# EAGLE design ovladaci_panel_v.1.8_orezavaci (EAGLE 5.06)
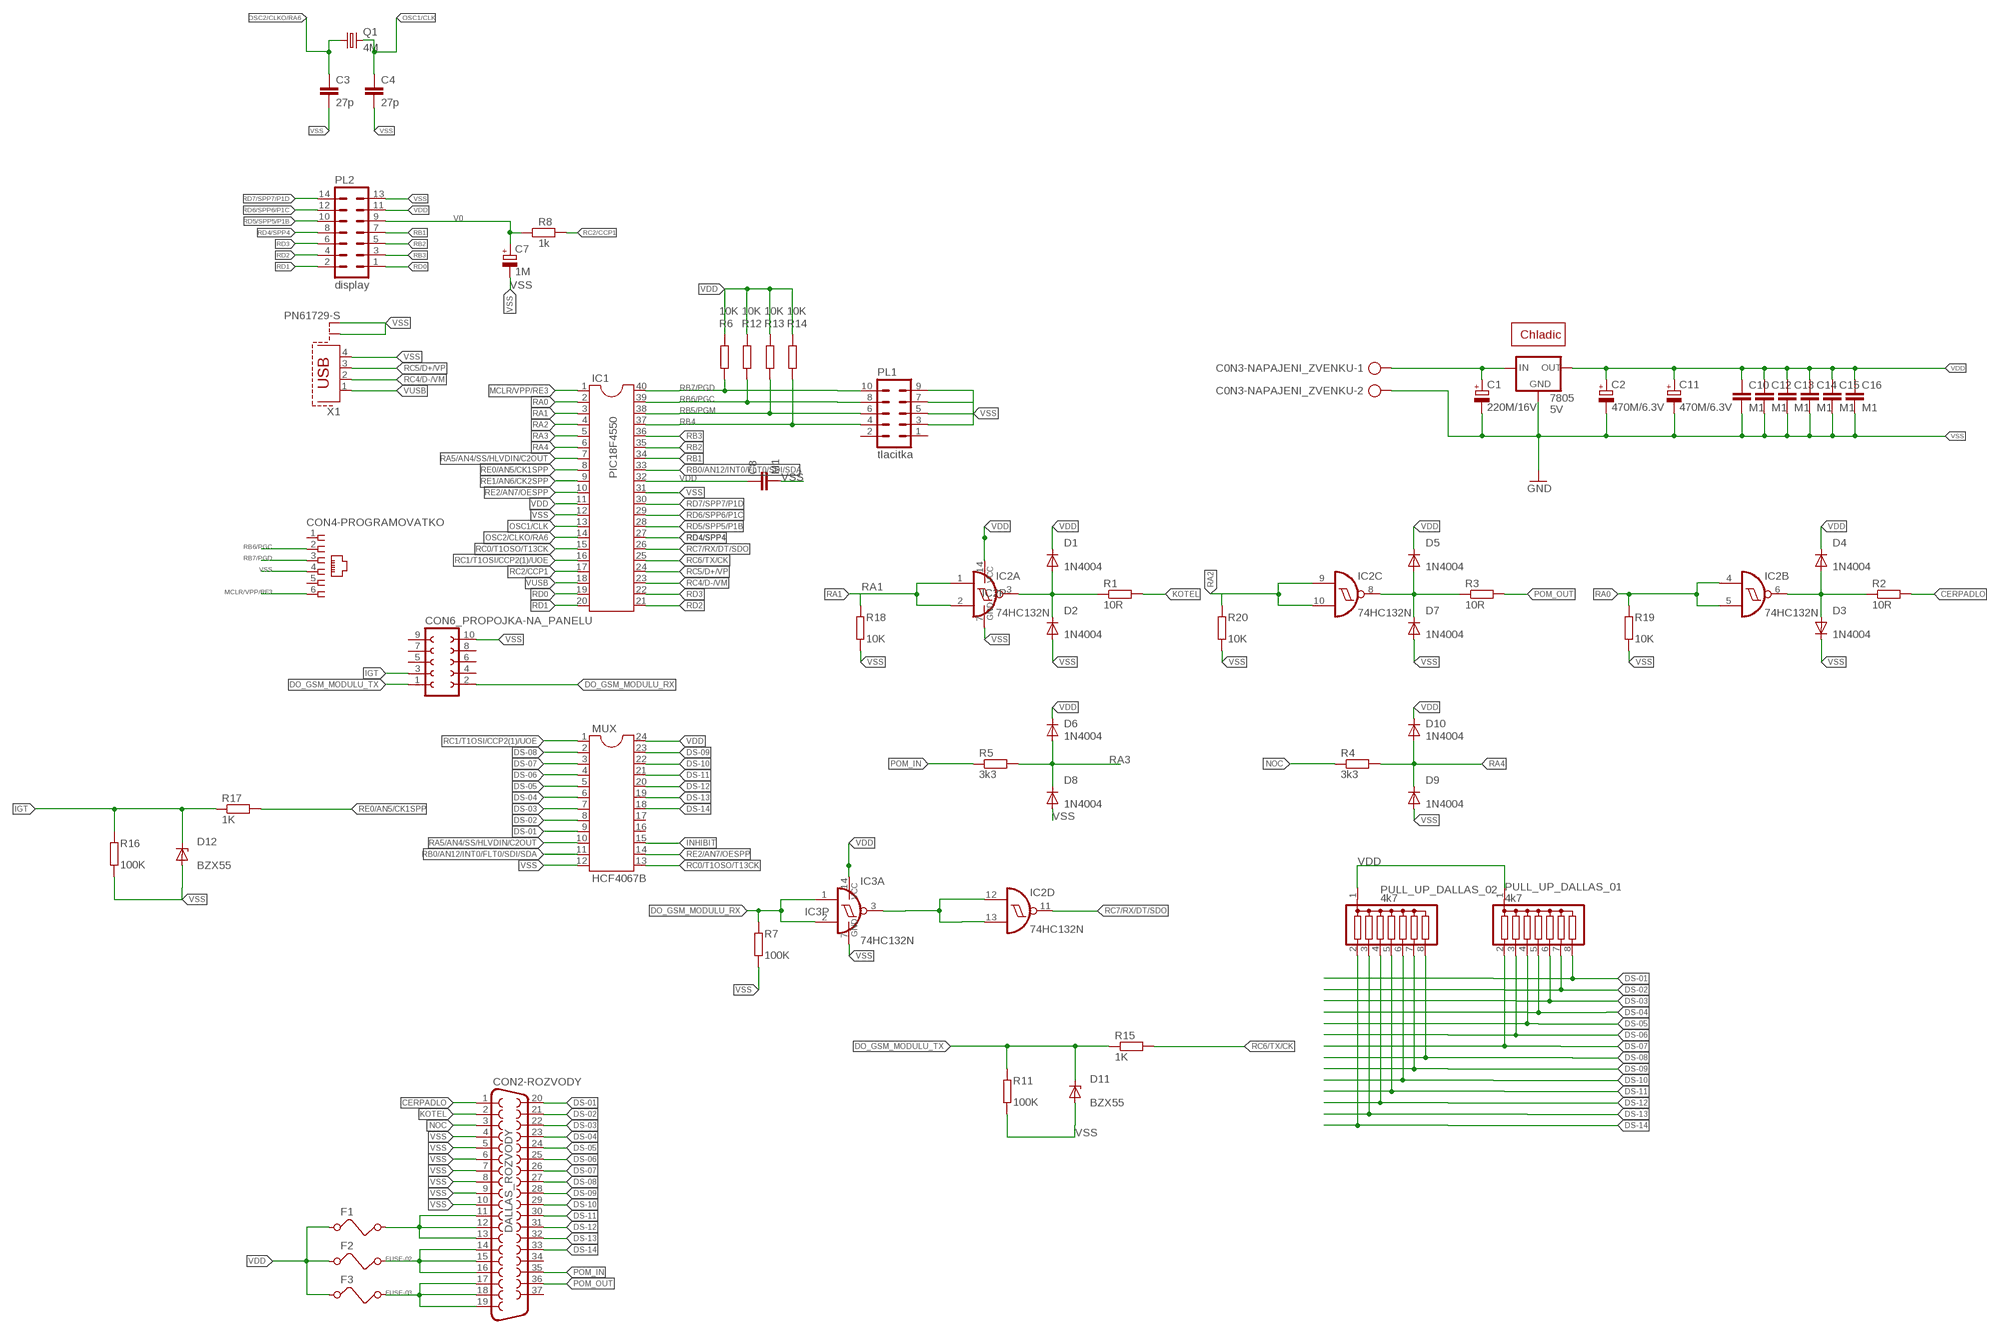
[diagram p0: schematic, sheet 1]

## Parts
7805  5V  78XXL  [78XXL]
C0N3-NAPAJENI_ZVENKU  AK500/2-H  [AK500/2-H]
C1  220M/16V  CPOL-EUE5-13  [E5-13]
C2  470M/6.3V  CPOL-EUE5-13  [E5-13]
C3  27p  C-EU025-025X050  [C025-025X050]
C4  27p  C-EU025-025X050  [C025-025X050]
C7  1M  CPOL-EUE2.5-5  [E2,5-5]
C8  M1  C-EU025-025X050  [C025-025X050]
C10  M1  C-EU025-025X050  [C025-025X050]
C11  470M/6.3V  CPOL-EUE5-13  [E5-13]
C12  M1  C-EU025-025X050  [C025-025X050]
C13  M1  C-EU025-025X050  [C025-025X050]
C14  M1  C-EU025-025X050  [C025-025X050]
C15  M1  C-EU025-025X050  [C025-025X050]
C16  M1  C-EU025-025X050  [C025-025X050]
CON2-ROZVODY  DALLAS_ROZVODY  F37HP  [F37HP]
CON4-PROGRAMOVATKO  520250-3  [520250-3]
CON6_PROPOJKA-NA_PANELU  FE05-2W  [FE05-2W]
D1  1N4004  [DO41-10]
D2  1N4004  [DO41-10]
D3  1N4004  [DO41-10]
D4  1N4004  [DO41-10]
D5  1N4004  [DO41-10]
D6  1N4004  [DO41-10]
D7  1N4004  [DO41-10]
D8  1N4004  [DO41-10]
D9  1N4004  [DO41-10]
D10  1N4004  [DO41-10]
D11  BZX55  [DO35Z10]
D12  BZX55  [DO35Z10]
F1  FUSE  [FUSE]
F2  FUSE  [FUSE]
F3  FUSE  [FUSE]
IC1  PIC18F4550  DIL40  [DIL40]
IC2  74HC132N  [DIL14]
IC3  74HC132N  [DIL14]
MUX  HCF4067B  DIL24-6  [DIL24-6]
PL1  tlacitka  10V  [10V]
PL2  display  14V  [14V]
PULL_UP_DALLAS_01  4k7  G07R  [SIL8]
PULL_UP_DALLAS_02  4k7  G07R  [SIL8]
Q1  4M  CRYSTALHC49S  [HC49/S]
R1  10R  R-EU_0207/10  [0207/10]
R2  10R  R-EU_0207/10  [0207/10]
R3  10R  R-EU_0207/10  [0207/10]
R4  3k3  R-EU_0207/10  [0207/10]
R5  3k3  R-EU_0207/10  [0207/10]
R6  10K  R-EU_0207/10  [0207/10]
R7  100K  R-EU_0207/10  [0207/10]
R8  1k  R-EU_0207/10  [0207/10]
R11  100K  R-EU_0207/10  [0207/10]
R12  10K  R-EU_0207/10  [0207/10]
R13  10K  R-EU_0207/10  [0207/10]
R14  10K  R-EU_0207/10  [0207/10]
R15  1K  R-EU_0207/10  [0207/10]
R16  100K  R-EU_0207/10  [0207/10]
R17  1K  R-EU_0207/10  [0207/10]
R18  10K  R-EU_0207/10  [0207/10]
R19  10K  R-EU_0207/10  [0207/10]
R20  10K  R-EU_0207/10  [0207/10]
U$1  CHLADIC  [CHLADIC]
X1  PN61729-S  [PN61729-S]

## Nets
CERPADLO: CON2-ROZVODY.1 R2.2
CESTA: IC2.12(D:I0) IC2.13(D:I1) IC3.3(A:O)
DO_GSM_MODULU_RX: CON6_PROPOJKA-NA_PANELU.2 IC3.1(A:I0) IC3.2(A:I1) R7.2
DO_GSM_MODULU_TX: CON6_PROPOJKA-NA_PANELU.1 D11.C R11.2 R15.1
DS-01: CON2-ROZVODY.20 MUX.9 PULL_UP_DALLAS_01.8
DS-02: CON2-ROZVODY.21 MUX.8 PULL_UP_DALLAS_01.7
DS-03: CON2-ROZVODY.22 MUX.7 PULL_UP_DALLAS_01.6
DS-04: CON2-ROZVODY.23 MUX.6 PULL_UP_DALLAS_01.5
DS-05: CON2-ROZVODY.24 MUX.5 PULL_UP_DALLAS_01.4
DS-06: CON2-ROZVODY.25 MUX.4 PULL_UP_DALLAS_01.3
DS-07: CON2-ROZVODY.26 MUX.3 PULL_UP_DALLAS_01.2
DS-08: CON2-ROZVODY.27 MUX.2 PULL_UP_DALLAS_02.8
DS-09: CON2-ROZVODY.28 MUX.23 PULL_UP_DALLAS_02.7
DS-10: CON2-ROZVODY.29 MUX.22 PULL_UP_DALLAS_02.6
DS-11: CON2-ROZVODY.30 MUX.21 PULL_UP_DALLAS_02.5
DS-12: CON2-ROZVODY.31 MUX.20 PULL_UP_DALLAS_02.4
DS-13: CON2-ROZVODY.32 MUX.19 PULL_UP_DALLAS_02.3
DS-14: CON2-ROZVODY.33 MUX.18 PULL_UP_DALLAS_02.2
FUSE-02: CON2-ROZVODY.14 CON2-ROZVODY.15 CON2-ROZVODY.16 F2.2
FUSE-03: CON2-ROZVODY.17 CON2-ROZVODY.18 CON2-ROZVODY.19 F3.2
IGT: CON6_PROPOJKA-NA_PANELU.3 D12.C R16.2 R17.1
INHIBIT: MUX.15
KOTEL: CON2-ROZVODY.2 R1.2
MCLR/VPP/RE3: CON4-PROGRAMOVATKO.6 IC1.1
N$1: 7805.IN C0N3-NAPAJENI_ZVENKU.1 C1.+
N$2: D1.A D2.C IC2.3(A:O) R1.1
N$5: D3.A D4.A IC2.6(B:O) R2.1
N$6: D5.A D7.C IC2.8(C:O) R3.1
N$10: CON2-ROZVODY.11 CON2-ROZVODY.12 CON2-ROZVODY.13 F1.2
NOC: CON2-ROZVODY.3 R4.1
OSC1/CLK: C4.1 IC1.13 Q1.2
OSC2/CLKO/RA6: C3.1 IC1.14 Q1.1
POM_IN: CON2-ROZVODY.35 R5.1
POM_OUT: CON2-ROZVODY.36 R3.2
RA0: IC1.2 IC2.4(B:I0) IC2.5(B:I1) R19.2
RA1: IC1.3 IC2.1(A:I0) IC2.2(A:I1) R18.2
RA2: IC1.4 IC2.9(C:I0) IC2.10(C:I1) R20.2
RA3: D6.A D8.C IC1.5 R5.2
RA4: D9.C D10.A IC1.6 R4.2
RA5/AN4/SS/HLVDIN/C2OUT: IC1.7 MUX.10
RB0/AN12/INT0/FLT0/SDI/SDA: IC1.33 MUX.11
RB1: IC1.34 PL2.7
RB2: IC1.35 PL2.5
RB3: IC1.36 PL2.3
RB4: IC1.37 PL1.4 R14.2
RB5/PGM: IC1.38 PL1.6 R13.2
RB6/PGC: CON4-PROGRAMOVATKO.2 IC1.39 PL1.8 R12.2
RB7/PGD: CON4-PROGRAMOVATKO.3 IC1.40 PL1.10 R6.2
RC0/T1OSO/T13CK: IC1.15 MUX.13
RC1/T1OSI/CCP2(1)/UOE: IC1.16 MUX.1
RC2/CCP1: IC1.17 R8.2
RC4/D-/VM: IC1.23 X1.2
RC5/D+/VP: IC1.24 X1.3
RC6/TX/CK: IC1.25 R15.2
RC7/RX/DT/SDO: IC1.26 IC2.11(D:O)
RD0: IC1.19 PL2.1
RD1: IC1.20 PL2.2
RD2: IC1.21 PL2.4
RD3: IC1.22 PL2.6
RD4/SPP4: IC1.27 PL2.8
RD5/SPP5/P1B: IC1.28 PL2.10
RD6/SPP6/P1C: IC1.29 PL2.12
RD7/SPP7/P1D: IC1.30 PL2.14
RE0/AN5/CK1SPP: IC1.8 R17.2
RE1/AN6/CK2SPP: IC1.9
RE2/AN7/OESPP: IC1.10 MUX.14
V0: C7.+ PL2.9 R8.1
VDD: 7805.OUT C2.+ C8.1 C10.1 C11.+ C12.1 C13.1 C14.1 C15.1 C16.1 D1.C D4.C D5.C D6.C D10.C F1.1 F2.1 F3.1 IC1.11 IC1.32 IC2.14(P:VCC) IC3.14(P:VCC) MUX.24 PL2.11 PULL_UP_DALLAS_01.1 PULL_UP_DALLAS_02.1 R6.1 R12.1 R13.1 R14.1
VSS: 7805.GND C0N3-NAPAJENI_ZVENKU.2 C1.- C2.- C3.2 C4.2 C7.- C8.2 C10.2 C11.- C12.2 C13.2 C14.2 C15.2 C16.2 CON2-ROZVODY.4 CON2-ROZVODY.5 CON2-ROZVODY.6 CON2-ROZVODY.7 CON2-ROZVODY.8 CON2-ROZVODY.9 CON2-ROZVODY.10 CON4-PROGRAMOVATKO.4 CON6_PROPOJKA-NA_PANELU.10 D2.A D3.C D7.A D8.A D9.A D11.A D12.A IC1.12 IC1.31 IC2.7(P:GND) IC3.7(P:GND) MUX.12 PL1.3 PL1.5 PL1.7 PL1.9 PL2.13 R7.1 R11.1 R16.1 R18.1 R19.1 R20.1 X1.4 X1.S1 X1.S2 ; supply symbol labelled GND
VUSB: IC1.18 X1.1
Unconnected: CON2-ROZVODY.34 CON2-ROZVODY.37 CON4-PROGRAMOVATKO.1 CON4-PROGRAMOVATKO.5 CON6_PROPOJKA-NA_PANELU.4 CON6_PROPOJKA-NA_PANELU.5 CON6_PROPOJKA-NA_PANELU.6 CON6_PROPOJKA-NA_PANELU.7 CON6_PROPOJKA-NA_PANELU.8 CON6_PROPOJKA-NA_PANELU.9 IC3.4(B:I0) IC3.5(B:I1) IC3.6(B:O) IC3.8(C:O) IC3.9(C:I0) IC3.10(C:I1) IC3.11(D:O) IC3.12(D:I0) IC3.13(D:I1) MUX.16 MUX.17 PL1.1 PL1.2

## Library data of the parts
7805 = v-reg:78XXL: VOLTAGE REGULATOR
C0N3-NAPAJENI_ZVENKU = con-ptr500:AK500/2-H: CONNECTOR
C1 C2 C7 C11 = rcl:CPOL-EU: POLARIZED CAPACITOR, European symbol
C3 C4 C8 C10 C12-C16 = rcl:C-EU: CAPACITOR, European symbol
CON2-ROZVODY = con-subd:F37: SUB-D
CON4-PROGRAMOVATKO = con-amp:520250-3: AMP connector
CON6_PROPOJKA-NA_PANELU = con-lsta:FE05-2W: FEMALE HEADER
D1-D10 = diode:1N4004: DIODE
D11 D12 = diode:BZX55: Z DIODE
F1-F3 = special:FUSE: FUSE
IC1 = ic-package:DIL40: Dual In Line pic
IC2 IC3 = 74xx-eu:74*132: Quad 2-input NAND schmitt trigger
MUX = ic-package:DIL24: Dual In Line
PL1 = con-harting-v:10V: CONNECTOR
PL2 = con-harting-v:14V: CONNECTOR
PULL_UP_DALLAS_01 PULL_UP_DALLAS_02 = resistor-sil:G07R: SIL RESISTOR
Q1 = crystal:CRYSTAL: CRYSTAL
R1-R8 R11-R20 = rcl:R-EU_: RESISTOR, European symbol
U$1 = chladic:CHLADIC: chadic
X1 = con-berg:PN61729-S: BERG USB connector

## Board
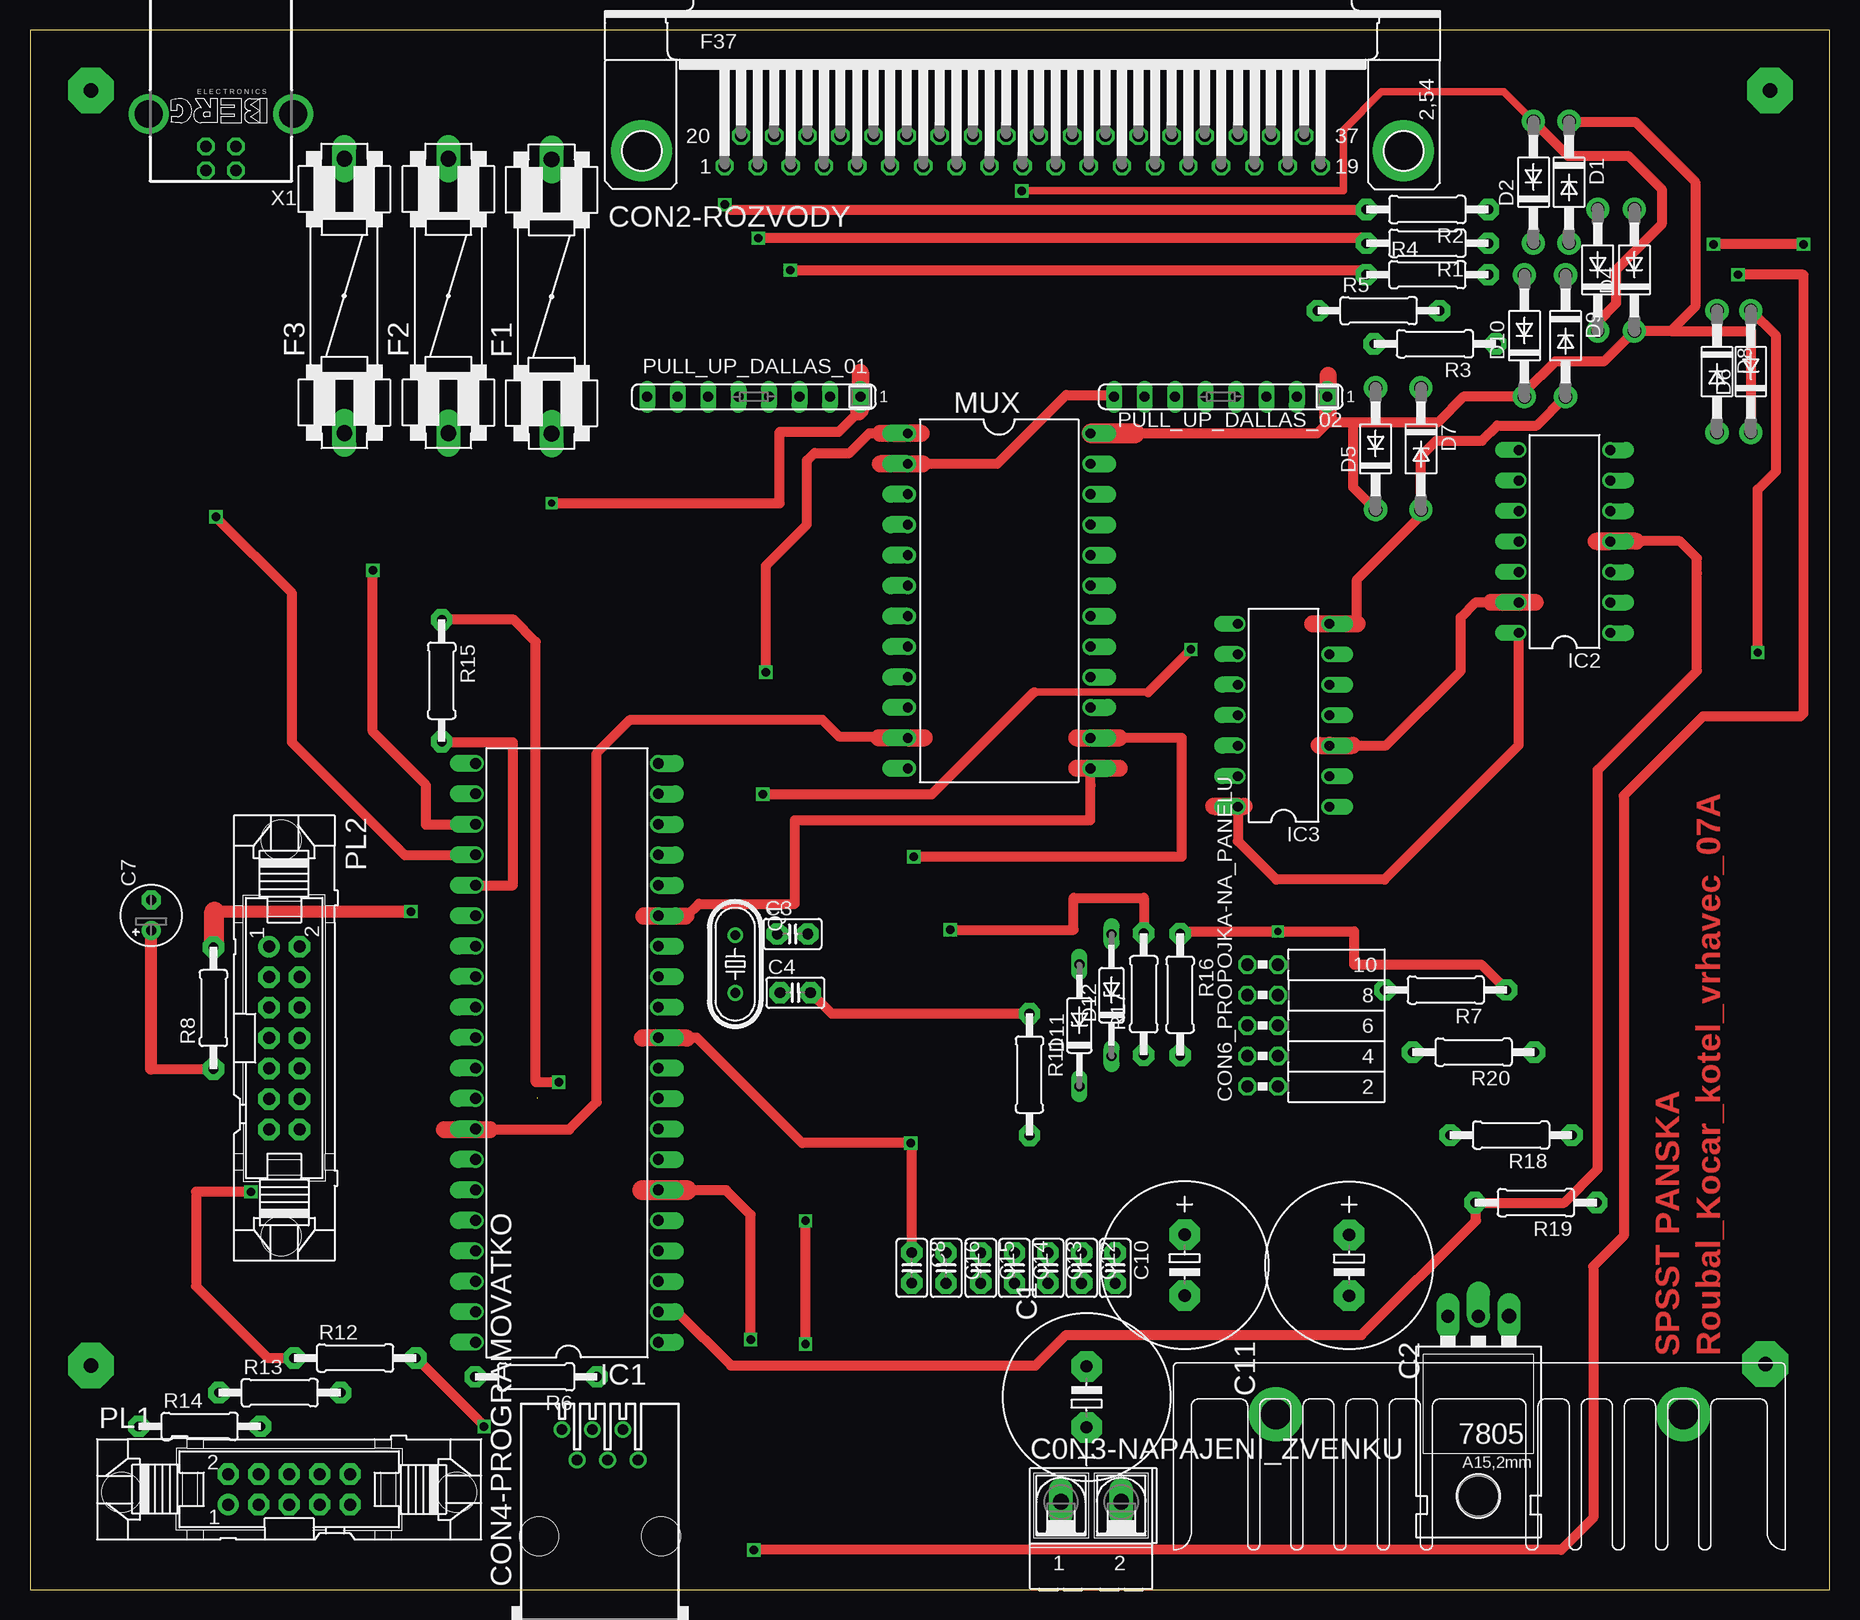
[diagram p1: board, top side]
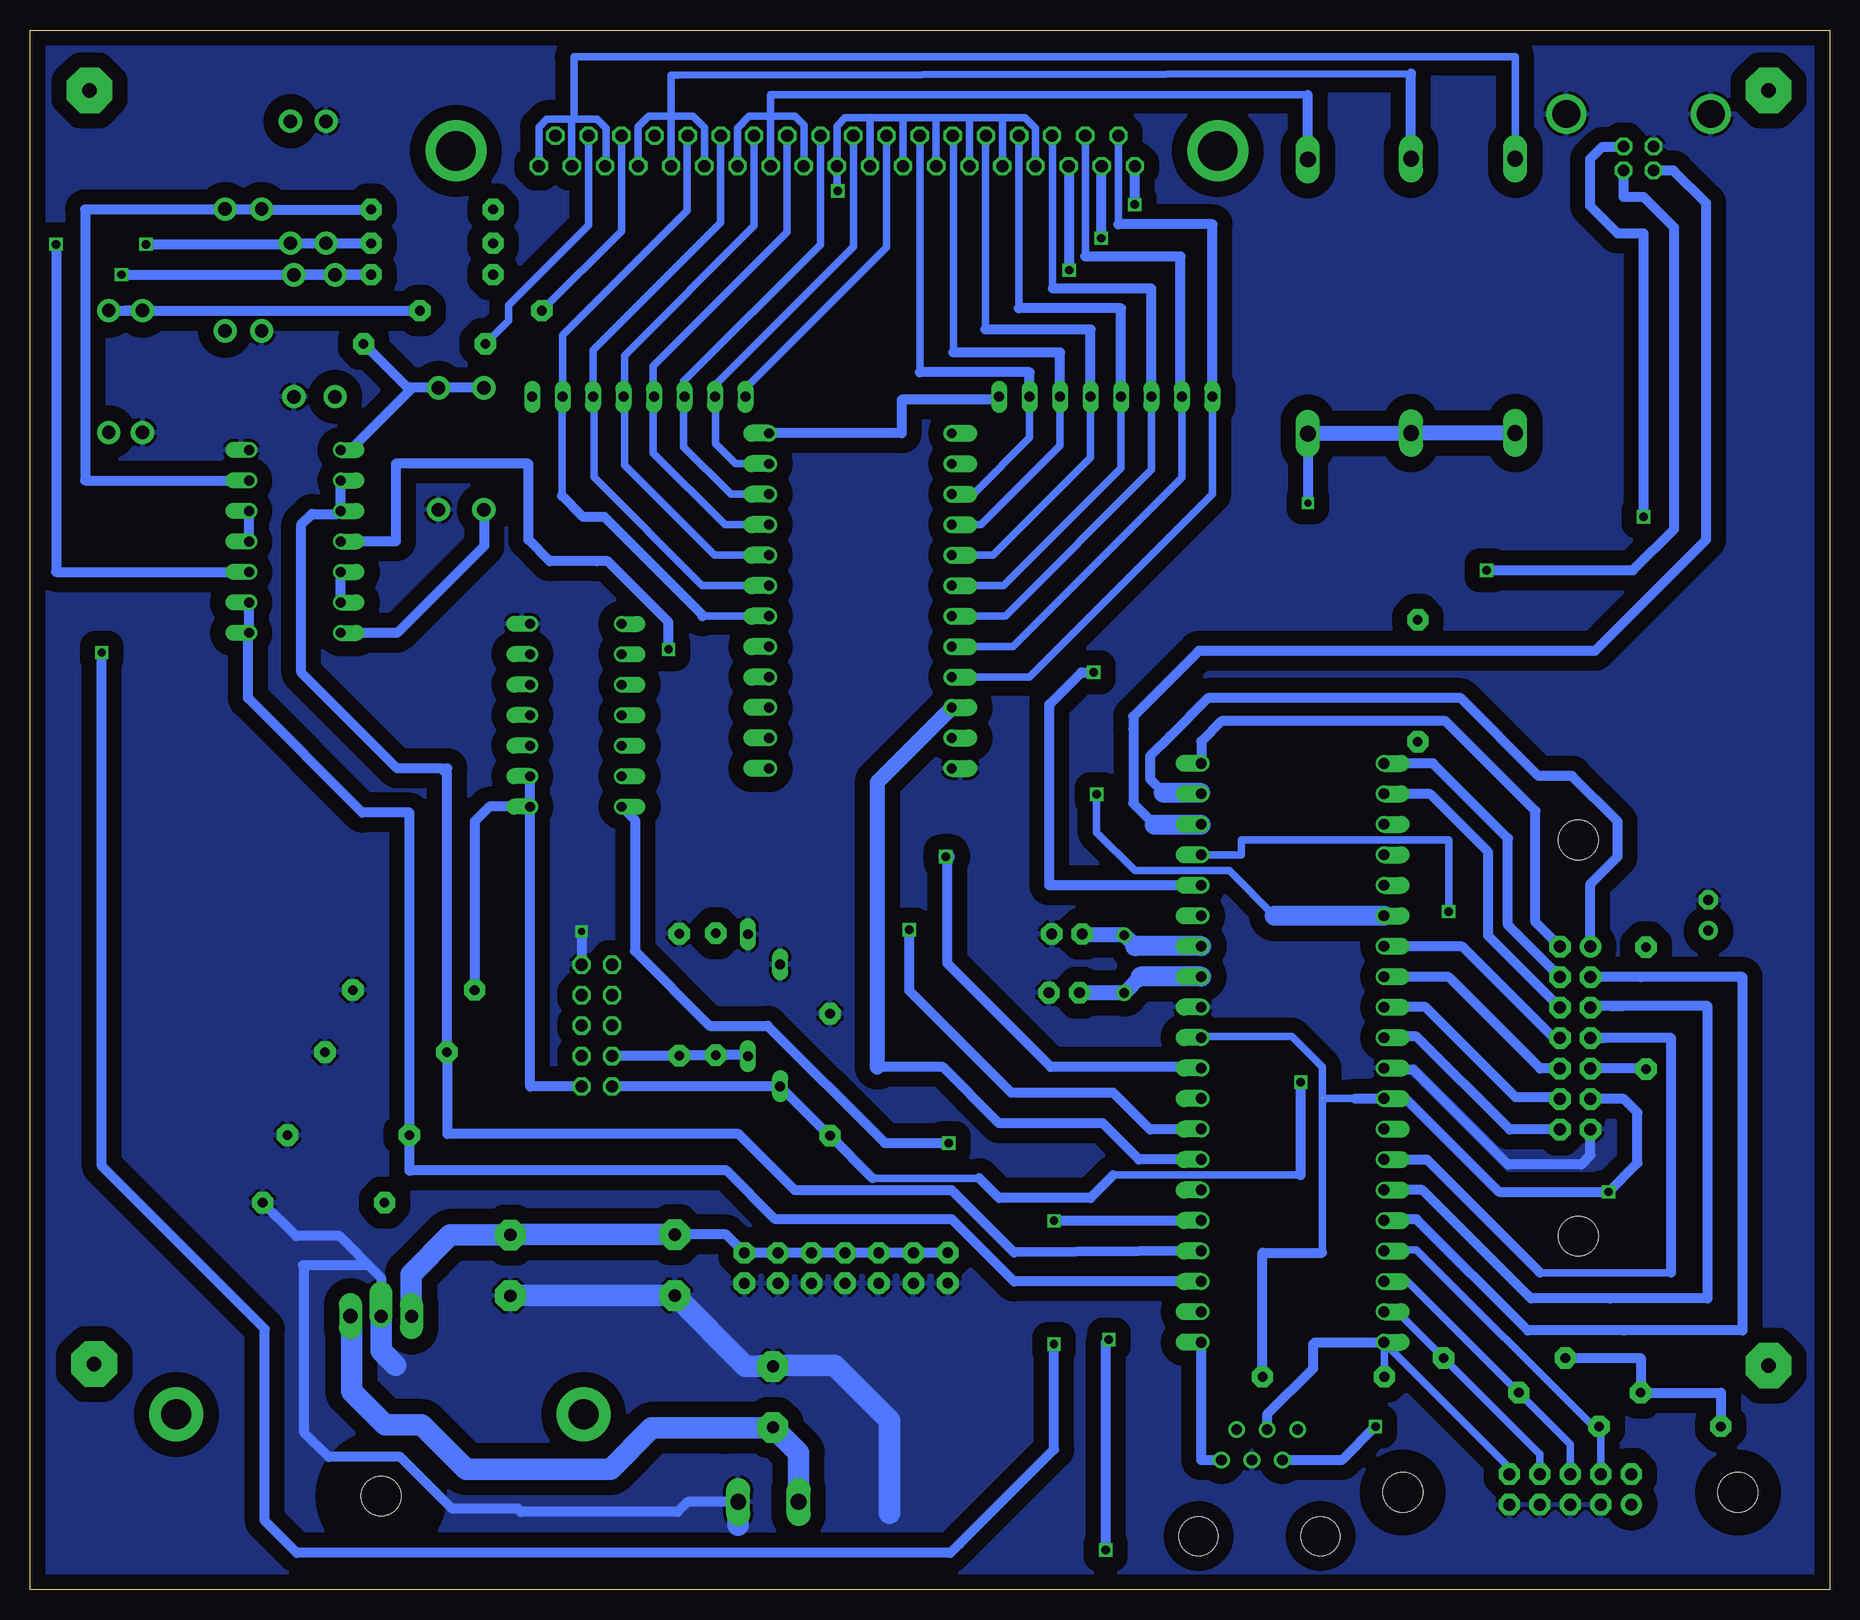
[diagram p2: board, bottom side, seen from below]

Size 150 x 130 mm. Coordinates in mm from the lower left corner, seen from the top.
Outline: 0,0 150,0 150,130 0,130 0,0
Copper layers (1*16): Top 0.035mm / dielectric 1.5mm / Bottom 0.035mm
Design rules "default *": minimum track width 0.2mm, minimum drill 24mil, track to track 8mil, track to pad 8mil, pad to pad 8mil, via to via 8mil, smd to smd 8mil, copper to edge 40mil, drill to drill 8mil, minimum pad ring 10mil, minimum via ring 8mil, stop-mask expansion 4mil, vias tented up to drill 0mil, thermal gap 10mil

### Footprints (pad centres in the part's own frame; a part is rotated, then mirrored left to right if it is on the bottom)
78XXL = drill 1.1 pad 1.93 offset: GND 0,-3.81 | drill 1.2 pad 1.93 long: IN -2.54,-3.81 | drill 1.1 pad 1.93 long: OUT 2.54,-3.81 | hole 3.302: 0,11.176
AK500/2-H = drill 1.321 long: 1 -2.515,0; 2 2.515,0
E5-13 = drill 1.016 pad 2.54 octagon: + -2.54,0; - 2.54,0
C025-025X050 = drill 0.9 pad 1.778 octagon: 1 -1.27,0; 2 1.27,0
E2,5-5 = drill 0.813 pad 1.6 round: + -1.27,0 | drill 0.813 pad 1.6 octagon: - 1.27,0
F37HP = drill 1.016 octagon: 1 -24.841,-1.27; 2 -22.073,-1.27; 3 -19.329,-1.27; 4 -16.561,-1.27; 5 -13.792,-1.27; 6 -11.049,-1.27; 7 -8.28,-1.27; 8 -5.512,-1.27; 9 -2.769,-1.27; 10 0,-1.27; 11 2.769,-1.27; 12 5.512,-1.27; 13 8.28,-1.27; 14 11.049,-1.27; 15 13.818,-1.27; 16 16.561,-1.27; 17 19.329,-1.27; 18 22.098,-1.27; 19 24.841,-1.27; 20 -23.47,1.27; 21 -20.701,1.27; 22 -17.932,1.27; 23 -15.189,1.27; 24 -12.421,1.27; 25 -9.652,1.27; 26 -6.909,1.27; 27 -4.14,1.27; 28 -1.372,1.27; 29 1.372,1.27; 30 4.14,1.27; 31 6.909,1.27; 32 9.677,1.27; 33 12.421,1.27; 34 15.189,1.27; 35 17.958,1.27; 36 20.701,1.27; 37 23.47,1.27 | drill 3.302 pad 5.08 round: G1 -31.75,0; G2 31.75,0
520250-3 = drill 0.889 round: 1 -3.175,8.89; 2 -1.905,6.35; 3 -0.635,8.89; 4 0.635,6.35; 5 1.905,8.89; 6 3.175,6.35 | hole 3.251: -5.08,0; 5.08,0
FE05-2W = drill 1.016 octagon: 1 -5.08,1.27; 2 -5.08,-1.27; 3 -2.54,1.27; 4 -2.54,-1.27; 5 0,1.27; 6 0,-1.27; 7 2.54,1.27; 8 2.54,-1.27; 9 5.08,1.27; 10 5.08,-1.27
DO41-10 = drill 1.118 pad 1.93 round: A 5.08,0; C -5.08,0
DO35Z10 = drill 0.813 long: A 5.08,0; C -5.08,0
FUSE = drill 1.321 long: 1 -11.43,0; 2 11.43,0
DIL40 = drill 0.9 offset: 1 -24.13,-7.62; 2 -21.59,-7.62; 3 -19.05,-7.62; 4 -16.51,-7.62; 5 -13.97,-7.62; 6 -11.43,-7.62; 7 -8.89,-7.62; 8 -6.35,-7.62; 9 -3.81,-7.62; 10 -1.27,-7.62; 11 1.27,-7.62; 12 3.81,-7.62; 13 6.35,-7.62; 14 8.89,-7.62; 15 11.43,-7.62; 16 13.97,-7.62; 17 16.51,-7.62; 18 19.05,-7.62; 19 21.59,-7.62; 20 24.13,-7.62; 21 24.13,7.62; 22 21.59,7.62; 23 19.05,7.62; 24 16.51,7.62; 25 13.97,7.62; 26 11.43,7.62; 27 8.89,7.62; 28 6.35,7.62; 29 3.81,7.62; 30 1.27,7.62; 31 -1.27,7.62; 32 -3.81,7.62; 33 -6.35,7.62; 34 -8.89,7.62; 35 -11.43,7.62; 36 -13.97,7.62; 37 -16.51,7.62; 38 -19.05,7.62; 39 -21.59,7.62; 40 -24.13,7.62
DIL14 = drill 0.813 offset: 1 -7.62,-3.81; 2 -5.08,-3.81; 3 -2.54,-3.81; 4 0,-3.81; 5 2.54,-3.81; 6 5.08,-3.81; 7 7.62,-3.81; 8 7.62,3.81; 9 5.08,3.81; 10 2.54,3.81; 11 0,3.81; 12 -2.54,3.81; 13 -5.08,3.81; 14 -7.62,3.81
DIL24-6 = drill 0.813 pad 1.422 offset: 1 -13.97,-7.62; 2 -11.43,-7.62; 3 -8.89,-7.62; 4 -6.35,-7.62; 5 -3.81,-7.62; 6 -1.27,-7.62; 7 1.27,-7.62; 8 3.81,-7.62; 9 6.35,-7.62; 10 8.89,-7.62; 11 11.43,-7.62; 12 13.97,-7.62; 13 13.97,7.62; 14 11.43,7.62; 15 8.89,7.62; 16 6.35,7.62; 17 3.81,7.62; 18 1.27,7.62; 19 -1.27,7.62; 20 -3.81,7.62; 21 -6.35,7.62; 22 -8.89,7.62; 23 -11.43,7.62; 24 -13.97,7.62
10V = drill 1 pad 1.778 round: 1 -5.08,-1.27 | drill 1 pad 1.778 octagon: 2 -5.08,1.27; 3 -2.54,-1.27; 4 -2.54,1.27; 5 0,-1.27; 6 0,1.27; 7 2.54,-1.27; 8 2.54,1.27; 9 5.08,-1.27; 10 5.08,1.27 | hole 3.302: 13.97,-0.254; -13.97,-0.254
14V = drill 1 pad 1.778 round: 1 -7.62,-1.27 | drill 1 pad 1.778 octagon: 2 -7.62,1.27; 3 -5.08,-1.27; 4 -5.08,1.27; 5 -2.54,-1.27; 6 -2.54,1.27; 7 0,-1.27; 8 0,1.27; 9 2.54,-1.27; 10 2.54,1.27; 11 5.08,-1.27; 12 5.08,1.27; 13 7.62,-1.27; 14 7.62,1.27 | hole 3.302: 16.51,-0.254; -16.51,-0.254
SIL8 = drill 0.813 long: 1 -8.89,0; 2 -6.35,0; 3 -3.81,0; 4 -1.27,0; 5 1.27,0; 6 3.81,0; 7 6.35,0; 8 8.89,0
HC49/S = drill 0.813 round: 1 -2.413,0; 2 2.413,0
0207/10 = drill 0.8 pad 1.778 octagon: 1 -5.08,0; 2 5.08,0
CHLADIC = drill 2.5 pad 4.5 round: P$2 -17.5,-0.5; P$3 16.45,-0.5
PN61729-S = drill 0.95 octagon: 1 1.25,4.71; 2 -1.25,4.71; 3 -1.25,2.71; 4 1.25,2.71 | drill 2.3 pad 2.9 round: S1 -6.02,0; S2 6.02,0

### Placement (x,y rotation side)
7805  120.74,18.97 180 top
C0N3-NAPAJENI_ZVENKU  88.45,7.3 0 top
C1  88.07,16.06 90 top
C2  109.95,27.02 270 top
C3  63.56,54.64 0 top
C4  63.79,49.75 0 top
C7  10.09,56.2 90 top
C8  73.5,26.81 270 top
C10  90.46,26.8 270 top
C11  96.25,27.04 270 top
C12  87.66,26.8 270 top
C13  84.86,26.8 270 top
C14  82.06,26.8 270 top
C15  79.26,26.8 270 top
C16  76.36,26.8 270 top
CON2-ROZVODY  82.74,119.92 0 top
CON4-PROGRAMOVATKO  47.51,4.44 0 top
CON6_PROPOJKA-NA_PANELU  102.75,47.01 90 top
D1  128.29,117.31 270 top
D2  125.32,117.31 90 top
D3  130.68,109.99 90 top
D4  133.73,109.99 90 top
D5  112.17,95.09 90 top
D6  143.44,101.53 90 top
D7  115.95,95.09 270 top
D8  140.62,101.53 270 top
D9  127.99,104.51 270 top
D10  124.57,104.51 90 top
D11  87.47,47.02 90 top
D12  90.16,49.54 90 top
F1  43.48,107.78 90 top
F2  34.88,107.83 90 top
F3  26.2,107.84 90 top
IC1  44.76,44.74 90 top
IC2  127.91,87.36 90 top
IC3  104.49,72.88 90 top
MUX  80.78,82.41 270 top
PL1  21.6,8.35 0 top
PL2  21.19,45.97 270 top
PULL_UP_DALLAS_01  60.33,99.43 180 top
PULL_UP_DALLAS_02  99.25,99.43 180 top
Q1  58.79,52.13 270 top
R1  116.48,112.22 180 top
R2  116.48,115.03 180 top
R3  117.11,103.84 180 top
R4  116.48,109.6 0 top
R5  112.42,106.6 0 top
R6  42.19,17.73 180 top
R7  118.02,49.97 180 top
R8  15.29,48.47 90 top
R11  83.31,42.92 270 top
R12  27.1,19.3 0 top
R13  20.82,16.4 0 top
R14  14.14,13.6 0 top
R15  34.32,75.76 270 top
R16  95.87,49.59 270 top
R17  92.84,49.62 90 top
R18  123.45,37.88 180 top
R19  125.52,32.24 180 top
R20  120.33,44.8 180 top
U$1  120.31,14.09 180 top
X1  15.91,123 180 top

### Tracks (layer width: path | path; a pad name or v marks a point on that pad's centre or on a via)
CERPADLO  (via drill 0.7)
  Top 0.813: R2.2 58.32,115.03 v57.91,115.44
  Bottom 0.813: CON2-ROZVODY.1 57.9,115.45 v57.91,115.44
CESTA  (1 unrouted)
  Top 0.813: 110.24,70.36 113.03,70.36 119.25,76.58 119.25,81.03 120.52,82.3 121.79,82.3
  Top 1.422: 108.3,70.36 107.44,70.36 110.24,70.36 | IC2.13 125.46,82.28 125.48,82.3 121.79,82.3
  Bottom 0.813: IC2.13 IC2.12
DO_GSM_MODULU_RX
  Bottom 0.813: IC3.1 IC3.2 | CON6_PROPOJKA-NA_PANELU.2 108.3,41.93 IC3.1 | IC3.1 111.71,65.26 112.94,64.03 R7.2
DO_GSM_MODULU_TX  (via drill 0.7)
  Top 0.813: R15.1 40.32,80.84 42.16,78.99 42.16,42.29 v44.07,42.29
  Bottom 0.61: 44.07,34.54 55.5,34.54 59.69,34.54 | 70.87,34.29 79.76,34.29
  Bottom 0.813: CON6_PROPOJKA-NA_PANELU.1 98.8,41.94 D11.C 83.38,37.84 R11.2 79.76,34.29 | 44.07,34.54 v44.07,42.29 | 59.69,34.54 61.59,32.64 69.22,32.64 70.87,34.29
DS-01
  Bottom 0.61: MUX.9 73.15,76.07 66.67,76.07 51.44,91.31 PULL_UP_DALLAS_01.8 | 59.27,113.79 CON2-ROZVODY.20
  Bottom 0.813: 59.27,113.79 51.44,113.79 PULL_UP_DALLAS_01.8
DS-02
  Bottom 0.61: PULL_UP_DALLAS_01.7 53.98,92.7 68.07,78.61 73.15,78.61 MUX.8 | 62.04,111.12 CON2-ROZVODY.21
  Bottom 0.813: 62.04,111.12 54.1,111.12 54.1,99.43 PULL_UP_DALLAS_01.7
DS-03
  Bottom 0.61: PULL_UP_DALLAS_01.6 56.52,93.34 68.71,81.15 73.15,81.15 MUX.7 | 64.77,108.46 64.77,121.19
  Bottom 0.813: PULL_UP_DALLAS_01.6 56.52,108.46 64.77,108.46 | 64.77,121.19 CON2-ROZVODY.22
DS-04
  Bottom 0.61: PULL_UP_DALLAS_01.5 59.06,93.47 68.83,83.69 73.15,83.69 MUX.6 | 67.56,106.81 67.56,121.19
  Bottom 0.813: PULL_UP_DALLAS_01.5 59.06,106.81 67.56,106.81 | 67.56,121.19 CON2-ROZVODY.23
DS-05
  Bottom 0.61: PULL_UP_DALLAS_01.4 61.6,94.35 69.72,86.23 73.15,86.23 MUX.5 | 70.36,105.03 70.36,121.19
  Bottom 0.813: PULL_UP_DALLAS_01.4 61.6,105.03 70.36,105.03 | 70.36,121.19 CON2-ROZVODY.24
DS-06
  Bottom 0.61: PULL_UP_DALLAS_01.3 64.14,95.37 70.74,88.77 73.15,88.77 MUX.4 | 73.03,103.12 73.03,121.19
  Bottom 0.813: PULL_UP_DALLAS_01.3 64.14,103.12 73.03,103.12 | 73.03,121.19 CON2-ROZVODY.25
DS-07
  Bottom 0.61: PULL_UP_DALLAS_01.2 66.68,96 71.37,91.31 73.15,91.31 MUX.3 | 75.82,101.47 CON2-ROZVODY.26
  Bottom 0.813: PULL_UP_DALLAS_01.2 66.68,101.47 75.82,101.47 | CON2-ROZVODY.26
DS-08
  Top 0.813: 80.77,93.98 80.63,93.84 | 80.77,93.98 86.36,99.57 90.22,99.57 PULL_UP_DALLAS_02.8 | 74.42,93.85 80.64,93.85 80.77,93.98 | 70.88,93.84 72.89,93.84 72.9,93.85
  Top 1.422: 70.88,93.84 MUX.2 | 70.87,93.85 72.9,93.85 74.42,93.85
  Bottom 0.61: CON2-ROZVODY.27 78.6,111.9 90.3,100.2 90.3,99.5 PULL_UP_DALLAS_02.8
DS-09
  Bottom 0.61: MUX.23 91.17,93.84 92.84,95.5 92.84,99.36 PULL_UP_DALLAS_02.7 92.84,99.5 92.84,100.46 81.37,111.92 CON2-ROZVODY.28
DS-10
  Bottom 0.61: MUX.22 91.56,91.3 95.5,95.25 95.5,99.37 PULL_UP_DALLAS_02.6 95.5,99.49 95.5,100.71 84.11,112.1 CON2-ROZVODY.29
DS-11
  Bottom 0.61: MUX.21 92.06,88.76 98.04,94.74 98.04,99.37 PULL_UP_DALLAS_02.5 98.04,99.49 98.04,101.98 86.88,113.14 CON2-ROZVODY.30
DS-12
  Bottom 0.61: MUX.20 92.95,86.22 100.46,93.73 100.46,99.36 PULL_UP_DALLAS_02.4 100.46,99.5 100.46,102.87 89.65,113.68 CON2-ROZVODY.31
DS-13
  Bottom 0.61: MUX.19 93.97,83.68 103,92.71 103,99.36 PULL_UP_DALLAS_02.3 103.06,103.31 92.46,113.92 92.46,121.15 CON2-ROZVODY.32
DS-14
  Bottom 0.61: MUX.18 93.97,81.14 | 105.66,91.19 105.66,99.37 PULL_UP_DALLAS_02.2 105.6,104.58 95.25,114.94 95.25,121.1 CON2-ROZVODY.33
  Bottom 0.813: 93.97,81.14 93.97,81.27 102.11,89.41 103.89,89.41 105.66,91.19
FUSE-02
  Bottom 0.61: CON2-ROZVODY.14 93.79,121.86 94.74,122.81 96.39,122.81 96.52,122.81 | 96.52,122.81 98.42,122.81 99.31,121.92 99.31,118.66 CON2-ROZVODY.16 | 96.56,122.3 96.56,122.77 96.52,122.81 | 96.56,122.3 CON2-ROZVODY.15 | 34.88,126.36 96.01,126.24 96.56,126.24 96.56,122.3
  Bottom 0.813: F2.2 34.88,126.36
FUSE-03
  Bottom 0.61: CON2-ROZVODY.19 107.58,121.91 106.93,122.56 105.16,122.56 | 104.65,122.56 102.74,122.56 101.98,121.79 101.98,118.74 CON2-ROZVODY.17 | 104.65,122.56 105.16,122.56 | CON2-ROZVODY.18 104.84,122.36 104.65,122.56 | F3.2 26.2,127.76 104.65,127.76 104.65,122.56 | 104.65,122.56 105.16,122.56
IGT
  Bottom 0.813: CON6_PROPOJKA-NA_PANELU.3 95.91,44.47 R16.2 92.87,44.51 R17.1 90.24,44.54 D12.C
KOTEL  (via drill 0.7)
  Top 0.813: v60.71,112.65 60.71,112.69 110.93,112.69 R1.2
  Bottom 0.813: CON2-ROZVODY.2 60.67,112.65 v60.71,112.65
MCLR/VPP/RE3
  Bottom 0.813: IC1.1 52.38,10.79 CON4-PROGRAMOVATKO.6
N$1
  Bottom 1.778: C0N3-NAPAJENI_ZVENKU.1 85.93,11.38 C1.+ 88.13,13.46 92.08,13.46 98.17,13.46 101.6,10.03 113.67,10.03 117.35,13.72 120.4,13.72 123.19,16.51 123.19,22.69 7805.IN
N$2  (via drill 0.7)
  Top 0.813: v147.83,112.14 v140.34,112.14
  Bottom 0.813: R1.1 D2.C D1.A 128.29,112.14 v140.34,112.14 | IC2.3 147.83,84.82 v147.83,112.14
N$3  (via drill 1.2 pad 3.81)
  other vias: 5.08,124.97
N$4  (via drill 1.2 pad 3.81)
  other vias: 145.03,124.97
N$5
  Bottom 0.61: D3.A 130.52,115.03
  Bottom 0.813: 130.52,115.03 R2.1 | D3.A D4.A 145.41,115.06 145.41,92.44 IC2.6
N$6
  Bottom 0.813: D5.A D7.C 118.11,100.17 | 118.11,100.17 118.53,100.17 R3.1 | IC2.8 123.3,94.98 118.11,100.17
N$8  (via drill 1.2 pad 3.81)
  other vias: 5.08,18.67
N$9  (via drill 1.2 pad 3.81)
  other vias: 144.65,18.8
N$10
  Bottom 0.61: CON2-ROZVODY.13 91.02,121.83 90.04,122.81 88.27,122.81 | 88.27,122.81 86.23,122.81 85.47,122.05 85.47,118.69 CON2-ROZVODY.11 | CON2-ROZVODY.12 88.25,122.8 88.27,122.81 | 43.48,124.59 86.11,124.59 88.27,124.59 88.27,122.81
  Bottom 0.813: F1.2 43.48,124.59
NOC  (via drill 0.7)
  Top 0.813: 111.02,109.98 R4.1 111.02,109.98 | v63.37,109.98 111.02,109.98
  Bottom 0.813: v63.37,109.98 63.37,118.65 CON2-ROZVODY.3
OSC1/CLK
  Bottom 1.27: 57.42,51.09 Q1.2 62.49,49.72 C4.1
  Bottom 1.676: IC1.13 57.42,51.09
OSC2/CLKO/RA6
  Bottom 1.27: 57.87,53.63 Q1.1 62.19,54.55 C3.1
  Bottom 1.676: IC1.14 57.87,53.63
POM_IN
  Bottom 0.61: CON2-ROZVODY.35 100.7,113.24 R5.1
POM_OUT
  Bottom 0.61: CON2-ROZVODY.36 103.44,113.73 110.11,107.06 110.11,105.76 R3.2
RA0
  Top 0.813: IC1.2 53.94,23.15 58.42,18.67 80.39,18.67 83.82,18.67 86.36,21.21 111,21.21 120.52,30.73 120.52,32.16 R19.2 127.88,32.24 130.68,35.05 130.68,68.33 138.94,76.58 138.94,84.71 138.94,85.98 137.54,87.38 133.86,87.38
  Top 1.422: IC2.4 130.57,87.36 130.56,87.38 133.86,87.38
  Bottom 0.813: IC2.4 IC2.5
RA1
  Bottom 0.813: IC1.3 67.98,25.69 73.15,30.86 87.88,30.86 91.95,34.92 118.24,34.92 | 118.24,34.92 118.36,34.92 | IC2.2 IC2.1 131.83,79.64 131.83,74.3 122.3,64.77 118.36,64.77 118.36,37.89 | 118.36,37.89 R18.2 | 118.36,37.89 118.36,35.05 118.24,34.92
RA2
  Bottom 0.813: IC1.4 67.98,28.1 73.15,33.27 86.23,33.27 90.93,37.97 115.19,37.97 115.19,44.74 R20.2 115.25,68 115.7,68.45 | 115.7,68.45 115.19,68.45 | 115.7,68.45 119.38,68.45 127.38,76.45 127.38,88.77 126.49,89.66 124.34,89.66 IC2.10 IC2.9
RA3  (via drill 0.7)
  Top 0.813: v64.64,20.45 v64.64,30.73 | v144.02,78.11 144.02,91.69 145.54,93.22 145.54,104.5 D6.A
  Bottom 0.813: R5.2 142.14,106.6 D8.C D6.A | IC1.5 64.61,30.77 v64.64,30.73 | v64.64,20.45 64.64,11.68 72.52,3.81 | 72.52,3.81 72.9,3.43 | v144.02,78.11 144.02,35.31 130.43,21.72 130.43,5.71 127.76,3.05 73.28,3.05 72.52,3.81
RA4  (via drill 0.7)
  Top 0.813: v142.37,109.6 147.83,109.6 147.83,73.03 147.57,72.77 139.45,72.77 132.84,66.17 132.84,29.46 130.3,26.92 130.3,5.97 127.64,3.3 v60.33,3.3 | v60.07,20.83 60.07,31.24 58.04,33.27 54.74,33.27
  Top 1.422: 52.38,33.27 IC1.6
  Top 1.676: 54.74,33.27 52.38,33.27 | 52.38,33.27 51.05,33.27 52.38,33.27
  Bottom 0.813: D9.C D10.A R4.2 | R4.2 | R4.2 142.36,109.59 v142.37,109.6 | v60.33,3.3 60.33,20.57 v60.07,20.83
RA5/AN4/SS/HLVDIN/C2OUT
  Bottom 0.813: IC1.7 57.56,35.85 60.58,38.86 69.22,38.86 73.91,43.56 79.38,43.56
  Bottom 1.27: 79.38,43.56 79.38,67.31 MUX.10
RB0/AN12/INT0/FLT0/SDI/SDA
  Top 0.813: 34.54,38.35 38.35,38.35 | 38.35,38.35 43.94,38.35 44.96,38.35 47.24,40.64 47.24,69.72 50.04,72.52 66.04,72.52 67.44,71.12 73.03,71.12 MUX.11 | 38.35,38.35 37.17,38.35 IC1.33
  Top 1.422: 34.54,38.35 38.35,38.35 | MUX.11 74.54,70.98 74.55,70.99 70.74,70.99
RB1
  Bottom 0.61: 13.21,26.42 24.13,26.42 24.26,26.54
  Bottom 0.813: PL2.7 18.79,45.97 | 24.13,26.42 24.26,26.54 33.53,35.81 37.1,35.81 IC1.34 | 13.21,26.42 13.21,45.97 PL2.7
  Bottom 1.016: PL2.7
RB2
  Bottom 0.813: IC1.35 33.94,33.31 24.89,24.26 18.29,24.26 10.16,24.26 10.16,48.64 18.16,48.64 | 18.16,48.64 17.27,48.64 | 18.16,48.64 19.79,48.64 PL2.5
RB3
  Bottom 0.813: IC1.36 37.04,30.86 34.42,30.86 25.15,21.59 17.14,21.59 7.24,21.59 7.24,51.05 15.74,51.05 PL2.3
RB4
  Bottom 0.61: PL1.4 19.06,12.97 19.06,13.44 R14.2 19.7,13.6 34.42,28.32 37.04,28.32 IC1.37
RB5/PGM
  Bottom 0.61: PL1.6 21.6,12.08 21.6,12.11 R13.2 35.28,25.78 35.31,25.78 37.04,25.78 IC1.38
RB6/PGC  (via drill 0.7)
  Top 0.813: v37.85,13.59 37.85,13.63 R12.2
  Bottom 0.61: PL1.8 24.14,11.32 24.2,11.32 R12.2 36.07,23.19 36.07,23.24 37.04,23.24 IC1.39
  Bottom 0.813: CON4-PROGRAMOVATKO.2 40.65,10.79 v37.85,13.59
RB7/PGD
  Bottom 0.61: PL1.10 26.68,10.15 IC1.40 37.1,20.58 R6.2
  Bottom 0.813: CON4-PROGRAMOVATKO.3 46.88,14.59 43.05,18.41 43.05,20.45 42.93,20.57 37.17,20.57 IC1.40
RC0/T1OSO/T13CK
  Top 0.813: 90.81,68.45 88.4,68.45 MUX.13 88.4,67.06 88.39,67.06 88.39,64.14 63.75,64.14 63.75,57.15 55.75,57.15 54.74,56.13
  Top 1.27: 54.61,56.13 54.74,56.13
  Top 1.422: 90.81,68.45 87.25,68.45 88.4,68.45 MUX.13 | IC1.15 51.21,56.17 51.18,56.13 54.61,56.13
RC1/T1OSI/CCP2(1)/UOE  (via drill 0.7)
  Top 0.813: v61.34,76.45 61.34,81.92 61.34,85.34 64.77,88.77 64.77,94.11 65.41,94.74 68.33,94.74 69.98,96.39 70.87,96.39
  Top 1.422: MUX.1 74.28,96.38 74.3,96.39 70.87,96.39
  Bottom 0.813: IC1.16 65.02,58.71 65.02,70.48 65.02,73.41 65.02,73.79 62.36,76.45 v61.34,76.45
RC2/CCP1  (via drill 0.7)
  Top 1.016: R8.2 15.37,53.55 | 15.37,56.52 v31.75,56.52
  Top 1.676: 15.37,53.55 15.37,56.52
  Bottom 0.61: v31.75,56.52 31.75,62.48 49.02,62.48 49.02,61.21 52.38,61.21
  Bottom 1.016: 52.38,61.21 IC1.17
RC4/D-/VM  (via drill 0.7)
  Top 0.813: IC1.23 37.13,63.75 33.02,63.75 33.02,67.06 28.57,71.5 v28.57,84.96
  Bottom 0.813: v28.57,84.96 16.38,84.96 12.95,88.39 12.95,113.54 15.49,116.08 17.16,116.08 X1.2
RC5/D+/VP  (via drill 0.7)
  Top 0.813: IC1.24 37.13,61.21 31.24,61.21 21.84,70.61 21.84,83.06 v15.49,89.41
  Bottom 0.813: v15.49,89.41 15.49,113.03 17.65,113.03 19.94,115.32 19.94,119.25 18.92,120.27 17.19,120.27 X1.3
RC6/TX/CK
  Top 0.813: IC1.25 40.26,58.71 40.26,70.61 34.32,70.61 R15.2
RC7/RX/DT/SDO  (via drill 0.7)
  Top 0.61: 83.69,74.8 93.22,74.8
  Top 0.813: v61.09,66.29 75.18,66.29 83.69,74.8 | 93.22,74.8 v96.77,78.36
  Bottom 0.61: 46.26,56.17 50.04,59.94 54.74,59.94 57.91,59.94 61.09,63.12 v61.09,66.29
  Bottom 0.813: v96.77,78.36 96.77,79.76 96.77,80.64 101.85,85.72 102.74,85.72 106.68,85.72 108.46,87.5 108.46,93.85 119.51,93.85 119.51,87.36 IC2.11
  Bottom 1.676: IC1.26 46.26,56.17
RD0
  Bottom 0.813: PL2.1 19.92,58.82 17.65,61.09 17.65,64.01 21.46,67.82 24.26,67.82 30.73,74.3 51.82,74.3 54.99,71.12 56.64,69.47 56.64,67.56 55.5,66.42 | 52.96,66.42 54.1,66.42 | 52.47,66.42 IC1.19
  Bottom 1.676: 52.47,66.42 52.96,66.42 55.5,66.42
RD1
  Bottom 0.813: IC1.20 52.38,70.69 50.67,72.39 32,72.39 24.51,64.9 24.51,55.64 PL2.2
RD2
  Bottom 0.813: IC1.21 33.05,68.87 26.8,62.61 26.8,55.38 PL2.4
RD3
  Bottom 0.813: PL2.6 22.47,48.51 28.45,54.48 28.45,61.47 33.27,66.29 37.1,66.29 IC1.22
RD4/SPP4
  Bottom 0.813: PL2.8 22.98,45.97 30.61,53.59 37.1,53.59 IC1.27
RD5/SPP5/P1B
  Bottom 0.813: PL2.10 24.12,43.43 31.75,51.05 37.1,51.05 IC1.28
RD6/SPP6/P1C
  Bottom 0.813: IC1.29 33.69,48.55 26.16,41.02 22.59,41.02 PL2.12
RD7/SPP7/P1D
  Bottom 0.813: PL2.14 26.66,38.35 34.42,46.1 37.04,46.1 IC1.30
RE0/AN5/CK1SPP  (via drill 0.7)
  Top 0.813: v76.71,54.99 87,54.99 87,57.66 92.84,57.66 R17.2
  Bottom 0.61: IC1.8 52.41,38.35
  Bottom 0.813: 52.41,38.35 56.64,38.35 59.69,41.4 68.2,41.4 76.71,49.91 v76.71,54.99
RE2/AN7/OESPP  (via drill 0.7)
  Top 0.813: v73.66,61.09 88.77,61.09 96.01,61.09 96.01,70.99 92.08,70.99 | 92.08,70.99 91.45,70.99 91.45,70.98 | 92.08,70.99 87.25,70.99
  Top 1.422: MUX.14 88.4,70.99 90.81,70.99 87.25,70.99
  Bottom 0.813: v73.66,61.09 73.53,60.96 73.53,52.2 64.9,43.56 52.38,43.56
  Bottom 1.27: v73.66,61.09 73.53,61.09 | IC1.10 52.38,43.56
V0
  Top 0.813: 10.09,43.56 10.09,43.94 | 10.09,43.56 10.09,43.43 10.09,43.56 | 10.09,43.56 10.09,44.45 | R8.1 10.27,43.39 10.09,43.56
  Top 1.016: 10.09,43.43 10.09,43.56 10.09,43.94 10.09,44.45 C7.+
  Bottom 0.813: PL2.9 15.33,43.43 R8.1
VDD  (via drill 0.6, 0.7)  (1 unrouted)
  Top 0.813: 55.74,45.84 55.57,46.01 | 136.79,104.91 D4.C 131.19,102.36 127.13,102.36 124.57,99.8 D10.C 119.5,99.43 117.35,97.28 110.29,97.28 | 136.79,104.91 138.81,106.93 138.81,117.35 133.86,122.3 128.38,122.3 D1.C | 136.79,104.91 143.44,104.91 D6.C | IC2.14 124.08,79.72 124.08,70.36 112.9,59.18 103.89,59.18 100.68,62.38 100.71,62.38 100.71,65.28 | v18.41,33.15 13.84,33.15 13.84,25.27 19.82,19.3 R12.1 | 88.52,96.39 89.15,96.39 89.15,96.38 MUX.24 | 69.09,98.17 67.44,96.52 62.48,96.52 62.48,90.55 62.1,90.55 46.35,90.55 v43.48,90.55 | 54.74,45.97 55.6,45.97 55.74,45.84 | C8.1 73.5,37.18 v73.41,37.21 64.36,37.21 55.74,45.84 | 108.2,97.28 108.2,101.22 | 110.29,97.28 108.2,97.28 | 110.29,97.28 110.29,91.89 D5.C | 92.08,96.38 107.3,96.38 108.2,97.28
  Top 1.422: IC3.14 100.68,65.28 98.68,65.28 100.71,65.28 | 100.71,65.28 101.22,65.28 100.71,65.28 | IC1.11 51.09,46.01 51.05,45.97 54.74,45.97 | PULL_UP_DALLAS_01.1 69.22,101.47 69.22,98.3 69.09,98.17 | PULL_UP_DALLAS_02.1 108.2,99.43 108.2,97.66 108.2,101.22
  Top 1.676: 88.52,96.39 92.08,96.38
  Bottom 0.61: 42.29,28.07 42.29,41.02 | 42.74,44.01 42.55,43.81 | 42.74,44.01 44.83,46.1 52.28,46.1 IC1.11 | 39.53,40.93 42.29,40.93 42.29,42.67 42.29,43.56 42.74,44.01
  Bottom 0.813: IC1.32 37.1,40.89 | PL2.11 17.14,40.89 16,39.75 16,35.56 v18.41,33.15 27.56,33.15 35.31,40.89 37.1,40.89 | IC1.32 37.1,40.89 | C11.+ 91.97,29.58 C10.1 C12.1 C13.1 C14.1 C15.1 C16.1 73.51,28.07 C8.1 | R12.1 15.74,19.3 R13.1 9.06,16.4 R14.1 | IC2.14 119.4,79.74 112.14,87 112.14,89.99 D5.C | MUX.24 77.34,96.38 77.34,99.19 69.46,99.19 PULL_UP_DALLAS_01.1 | 39.53,40.93 IC1.32 | R6.1 47.27,28.07 42.29,28.07 | v73.41,37.21 78.74,37.21 88.52,46.99 93.34,46.99 99.57,53.21 99.57,64.14 IC3.14 | F1.1 v43.48,90.55
  Bottom 1.27: F1.1 34.88,96.35 F2.1 F3.1
  Bottom 1.778: 7805.OUT 118.24,22.82 118.24,26.29 114.97,29.56 C2.+ 109.93,29.58 C11.+
VSS  (via drill 0.6, 0.7)
  Top 0.61: v82.68,116.59 109.47,116.59 109.47,121.67 112.65,124.84 122.87,124.84 D2.A
  Top 0.813: D9.A 125.59,97.03 122.3,97.03 121.03,95.76 117.22,95.76 115.95,94.49 D7.A 115.95,89.53 115.89,89.47 110.62,84.2 110.62,80.52 | R11.1 66.81,48.01 C4.2 | D3.C 130.68,105.67 132.21,107.19 132.21,109.98 136.02,113.79 136.02,116.71 133.22,119.51 128.2,119.51 D2.A | R7.1 120.98,52.09 110.36,52.09 110.36,54.86 v104.01,54.86 95.87,54.86 R16.1
  Top 1.422: IC3.7 106.95,80.5 106.93,80.52 110.62,80.52
  Bottom 0.61: 68.96,122.68 67.06,122.68 66.17,121.79 66.17,118.66 CON2-ROZVODY.4 | 68.96,122.68 71.75,122.68 | 71.75,122.68 74.3,122.68 | 74.3,122.68 77.34,122.68 | 77.34,122.68 80.01,122.68 | 80.01,122.68 82.04,122.68 82.74,121.98 CON2-ROZVODY.10 82.74,116.59 v82.68,116.59 | CON2-ROZVODY.5 68.95,122.67 68.96,122.68 | CON2-ROZVODY.6 71.69,122.62 71.75,122.68 | CON2-ROZVODY.7 74.46,122.52 74.3,122.68 | CON2-ROZVODY.9 79.97,122.64 80.01,122.68 | CON2-ROZVODY.8 77.23,122.57 77.34,122.68
  Bottom 0.813: PL2.13 19.92,36.21 20.7,35.43 26.8,35.43 34.67,43.31 36.98,43.31 IC1.31 | 7805.GND 120.74,26 121.09,26.35 | 121.09,26.35 124.21,29.46 127.82,29.46 R19.1 | C0N3-NAPAJENI_ZVENKU.2 95.19,7.3 96.01,6.48 109.09,6.48 109.35,6.73 114.81,6.73 119.13,11.05 125.09,11.05 127.13,13.08 127.13,26.92 127.25,27.05 121.79,27.05 121.09,26.35 | v104.01,54.86 CON6_PROPOJKA-NA_PANELU.10
  Bottom 1.778: 120.78,22.74 7805.GND 120.74,19.9 119.51,18.67 | C0N3-NAPAJENI_ZVENKU.2 90.96,5.36 | 78.36,6.35 78.36,14.1 82.93,18.67 88,18.67 C1.- | C1.- 90.34,18.6 C11.- 109.93,24.5 C2.- | C1.- 89.02,18.67
  pour Bottom (isolate 1.27): 0,130 150,130 150.11,-0.13 0,-0.13
VUSB
  Bottom 0.813: 56.26,63.75 58.04,65.53 58.04,71.75 58.04,72.77 52.58,78.23 19.56,78.23 10.29,87.5 10.29,112.9 10.29,115.57 13.01,118.29 X1.1 | 52.41,63.75 IC1.18
  Bottom 1.676: 56.26,63.75 52.41,63.75

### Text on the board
Top: SPSST PANSKA | Roubal_Kocar_kotel_vrhavec_07A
